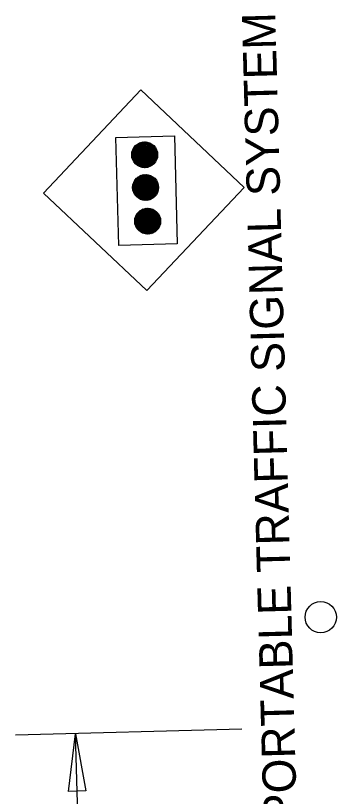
# Model space of a CAD drawing. Extents: x 1929624 to 1932070, y 596315 to 605533.
# Drawn here: x 1930139.3 to 1930198.2, y 598591.7 to 598735.3 of the extents above; entities that cross this region are included whole.
import ezdxf

# ---------------------------------------------------------------- set-up
doc = ezdxf.new("R2010")
doc.units = 0
doc.layers.add('Default', color=7, linetype='Continuous')

msp = doc.modelspace()

# ---------------------------------------------------------------- linework, layer by layer
at = {"layer": 'Default'}
for p, q in [((1930144.38, 598702.64), (1930162.31, 598721.62)), ((1930162.31, 598721.62), (1930181.29, 598703.69)), ((1930162.83, 598712.07), (1930160.61, 598709.73)), ((1930162.98, 598712.07), (1930160.61, 598709.58)), ((1930162.67, 598712.05), (1930160.62, 598709.89)), ((1930163.12, 598712.07), (1930160.63, 598709.44)), ((1930163.25, 598712.06), (1930160.64, 598709.31)), ((1930162.5, 598712.02), (1930160.64, 598710.06)), ((1930163.38, 598712.04), (1930160.67, 598709.19)), ((1930162.31, 598711.97), (1930160.68, 598710.25)), ((1930163.5, 598712.02), (1930160.7, 598709.07)), ((1930163.61, 598711.99), (1930160.73, 598708.95)), ((1930162.1, 598711.9), (1930160.74, 598710.47)), ((1930163.72, 598711.96), (1930160.77, 598708.84)), ((1930161.83, 598711.77), (1930160.85, 598710.74)), ((1930163.94, 598711.88), (1930160.86, 598708.64)), ((1930164.03, 598711.84), (1930160.91, 598708.54)), ((1930164.13, 598711.79), (1930160.96, 598708.45)), ((1930164.22, 598711.73), (1930161.02, 598708.36)), ((1930164.31, 598711.68), (1930161.08, 598708.27)), ((1930164.4, 598711.62), (1930161.15, 598708.19)), ((1930161.38, 598711.44), (1930161.16, 598711.21)), ((1930164.48, 598711.55), (1930161.22, 598708.11)), ((1930164.56, 598711.49), (1930161.29, 598708.03)), ((1930164.64, 598711.42), (1930161.36, 598707.96)), ((1930164.71, 598711.34), (1930161.44, 598707.89)), ((1930164.78, 598711.27), (1930161.52, 598707.82)), ((1930164.85, 598711.19), (1930161.6, 598707.76)), ((1930164.91, 598711.11), (1930161.69, 598707.7)), ((1930164.97, 598711.02), (1930161.78, 598707.64)), ((1930165.03, 598710.93), (1930161.87, 598707.59)), ((1930165.09, 598710.84), (1930161.97, 598707.54)), ((1930165.14, 598710.74), (1930162.07, 598707.5)), ((1930165.18, 598710.64), (1930162.17, 598707.46)), ((1930165.23, 598710.53), (1930162.28, 598707.42)), ((1930165.26, 598710.42), (1930162.39, 598707.39)), ((1930165.3, 598710.31), (1930162.51, 598707.36)), ((1930165.33, 598710.19), (1930162.63, 598707.34)), ((1930165.35, 598710.06), (1930162.75, 598707.32)), ((1930165.37, 598709.93), (1930162.89, 598707.31)), ((1930165.38, 598709.79), (1930163.03, 598707.31)), ((1930165.38, 598709.64), (1930163.18, 598707.32)), ((1930165.37, 598709.48), (1930163.34, 598707.33)), ((1930165.35, 598709.3), (1930163.51, 598707.37)), ((1930165.31, 598709.11), (1930163.7, 598707.42)), ((1930165.24, 598708.89), (1930163.92, 598707.5)), ((1930165.12, 598708.61), (1930164.19, 598707.63)), ((1930163.06, 598706.05), (1930160.77, 598703.64)), ((1930163.2, 598706.05), (1930160.78, 598703.5)), ((1930162.9, 598706.04), (1930160.78, 598703.79)), ((1930163.34, 598706.04), (1930160.79, 598703.36)), ((1930162.74, 598706.01), (1930160.79, 598703.96)), ((1930163.47, 598706.03), (1930160.81, 598703.23)), ((1930162.56, 598705.97), (1930160.82, 598704.14)), ((1930163.59, 598706.01), (1930160.84, 598703.11)), ((1930163.71, 598705.99), (1930160.87, 598702.99)), ((1930162.36, 598705.91), (1930160.87, 598704.35)), ((1930163.82, 598705.96), (1930160.91, 598702.88)), ((1930163.93, 598705.92), (1930160.95, 598702.77)), ((1930162.12, 598705.81), (1930160.96, 598704.59)), ((1930164.04, 598705.88), (1930160.99, 598702.67)), ((1930164.14, 598705.84), (1930161.04, 598702.57)), ((1930164.24, 598705.79), (1930161.1, 598702.47)), ((1930161.8, 598705.63), (1930161.13, 598704.92)), ((1930164.33, 598705.74), (1930161.15, 598702.38)), ((1930164.43, 598705.69), (1930161.21, 598702.29)), ((1930164.51, 598705.63), (1930161.27, 598702.21)), ((1930164.6, 598705.57), (1930161.34, 598702.13)), ((1930164.68, 598705.5), (1930161.41, 598702.05)), ((1930164.76, 598705.43), (1930161.48, 598701.98)), ((1930164.83, 598705.36), (1930161.56, 598701.9)), ((1930164.9, 598705.29), (1930161.63, 598701.84)), ((1930164.97, 598705.21), (1930161.71, 598701.77)), ((1930165.04, 598705.13), (1930161.8, 598701.71)), ((1930165.1, 598705.04), (1930161.89, 598701.65)), ((1930165.16, 598704.96), (1930161.98, 598701.6)), ((1930165.22, 598704.86), (1930162.07, 598701.55)), ((1930165.27, 598704.77), (1930162.17, 598701.5)), ((1930165.32, 598704.67), (1930162.27, 598701.46)), ((1930165.36, 598704.57), (1930162.38, 598701.42)), ((1930165.4, 598704.46), (1930162.49, 598701.38)), ((1930165.44, 598704.35), (1930162.6, 598701.35)), ((1930165.47, 598704.23), (1930162.72, 598701.33)), ((1930165.5, 598704.11), (1930162.84, 598701.31)), ((1930165.52, 598703.98), (1930162.97, 598701.29)), ((1930165.53, 598703.84), (1930163.11, 598701.29)), ((1930144.38, 598702.64), (1930163.36, 598684.73)), ((1930165.54, 598703.7), (1930163.25, 598701.29)), ((1930163.36, 598684.73), (1930181.29, 598703.69)), ((1930165.54, 598703.54), (1930163.41, 598701.3)), ((1930165.52, 598703.38), (1930163.57, 598701.32)), ((1930165.49, 598703.2), (1930163.75, 598701.36)), ((1930165.44, 598702.99), (1930163.95, 598701.42)), ((1930165.36, 598702.75), (1930164.19, 598701.52)), ((1930165.19, 598702.42), (1930164.51, 598701.71)), ((1930163.44, 598699.85), (1930161.16, 598697.44)), ((1930163.59, 598699.85), (1930161.16, 598697.3)), ((1930163.29, 598699.84), (1930161.16, 598697.6)), ((1930163.72, 598699.85), (1930161.18, 598697.16)), ((1930163.12, 598699.82), (1930161.18, 598697.76)), ((1930163.85, 598699.83), (1930161.2, 598697.04)), ((1930162.94, 598699.78), (1930161.21, 598697.95)), ((1930163.98, 598699.82), (1930161.23, 598696.91)), ((1930164.1, 598699.79), (1930161.26, 598696.79)), ((1930162.74, 598699.72), (1930161.26, 598698.15)), ((1930164.21, 598699.76), (1930161.29, 598696.68)), ((1930164.32, 598699.72), (1930161.33, 598696.58)), ((1930162.51, 598699.62), (1930161.34, 598698.39)), ((1930164.42, 598699.69), (1930161.38, 598696.47)), ((1930164.53, 598699.64), (1930161.43, 598696.37)), ((1930164.62, 598699.6), (1930161.48, 598696.28)), ((1930164.72, 598699.54), (1930161.54, 598696.19)), ((1930164.81, 598699.49), (1930161.6, 598696.1)), ((1930162.19, 598699.43), (1930161.51, 598698.72)), ((1930164.9, 598699.43), (1930161.66, 598696.01)), ((1930164.98, 598699.37), (1930161.72, 598695.93)), ((1930165.06, 598699.31), (1930161.79, 598695.85)), ((1930165.14, 598699.24), (1930161.86, 598695.78)), ((1930165.22, 598699.17), (1930161.94, 598695.71)), ((1930165.29, 598699.09), (1930162.02, 598695.64)), ((1930165.36, 598699.01), (1930162.1, 598695.58)), ((1930165.42, 598698.93), (1930162.18, 598695.51)), ((1930165.49, 598698.85), (1930162.27, 598695.46)), ((1930165.55, 598698.76), (1930162.36, 598695.4)), ((1930165.6, 598698.67), (1930162.46, 598695.35)), ((1930165.65, 598698.57), (1930162.56, 598695.3)), ((1930165.7, 598698.47), (1930162.66, 598695.26)), ((1930165.75, 598698.37), (1930162.76, 598695.22)), ((1930165.79, 598698.26), (1930162.87, 598695.19)), ((1930165.83, 598698.15), (1930162.99, 598695.16)), ((1930165.86, 598698.03), (1930163.1, 598695.13)), ((1930165.88, 598697.91), (1930163.23, 598695.11)), ((1930165.9, 598697.78), (1930163.36, 598695.1)), ((1930165.92, 598697.65), (1930163.5, 598695.09)), ((1930165.92, 598697.5), (1930163.64, 598695.09)), ((1930165.92, 598697.35), (1930163.79, 598695.1)), ((1930165.91, 598697.18), (1930163.96, 598695.13)), ((1930165.88, 598697), (1930164.14, 598695.17)), ((1930165.83, 598696.8), (1930164.34, 598695.23)), ((1930165.74, 598696.56), (1930164.57, 598695.33)), ((1930165.57, 598696.23), (1930164.89, 598695.51)), ((1930139.26, 598602.99), (1930180.83, 598604.11)), ((1930149, 598592.59), (1930150.3, 598603.17)), ((1930151.22, 598568.73), (1930150.3, 598603.17)), ((1930150.3, 598603.17), (1930152.17, 598592.68)), ((1930152.17, 598592.68), (1930149, 598592.59))]:
    msp.add_line(p, q, dxfattribs=at)
msp.add_lwpolyline([(1930168.98, 598693.28), (1930158.22, 598692.99), (1930157.69, 598712.86), (1930168.45, 598713.15)], close=True, dxfattribs=at)
for centre, radius in [((1930162.99, 598709.69), 2.38), ((1930163.16, 598703.67), 2.38), ((1930163.54, 598697.47), 2.38), ((1930195.36, 598624.63), 2.88)]:
    msp.add_circle(centre, radius, dxfattribs=at)

# ---------------------------------------------------------------- texts
msp.add_text('PORTABLE TRAFFIC SIGNAL SYSTEM', height=6.1396, rotation=91.5377, dxfattribs=at).set_placement((1930191, 598586.83))

doc.saveas('drawing.dxf')
